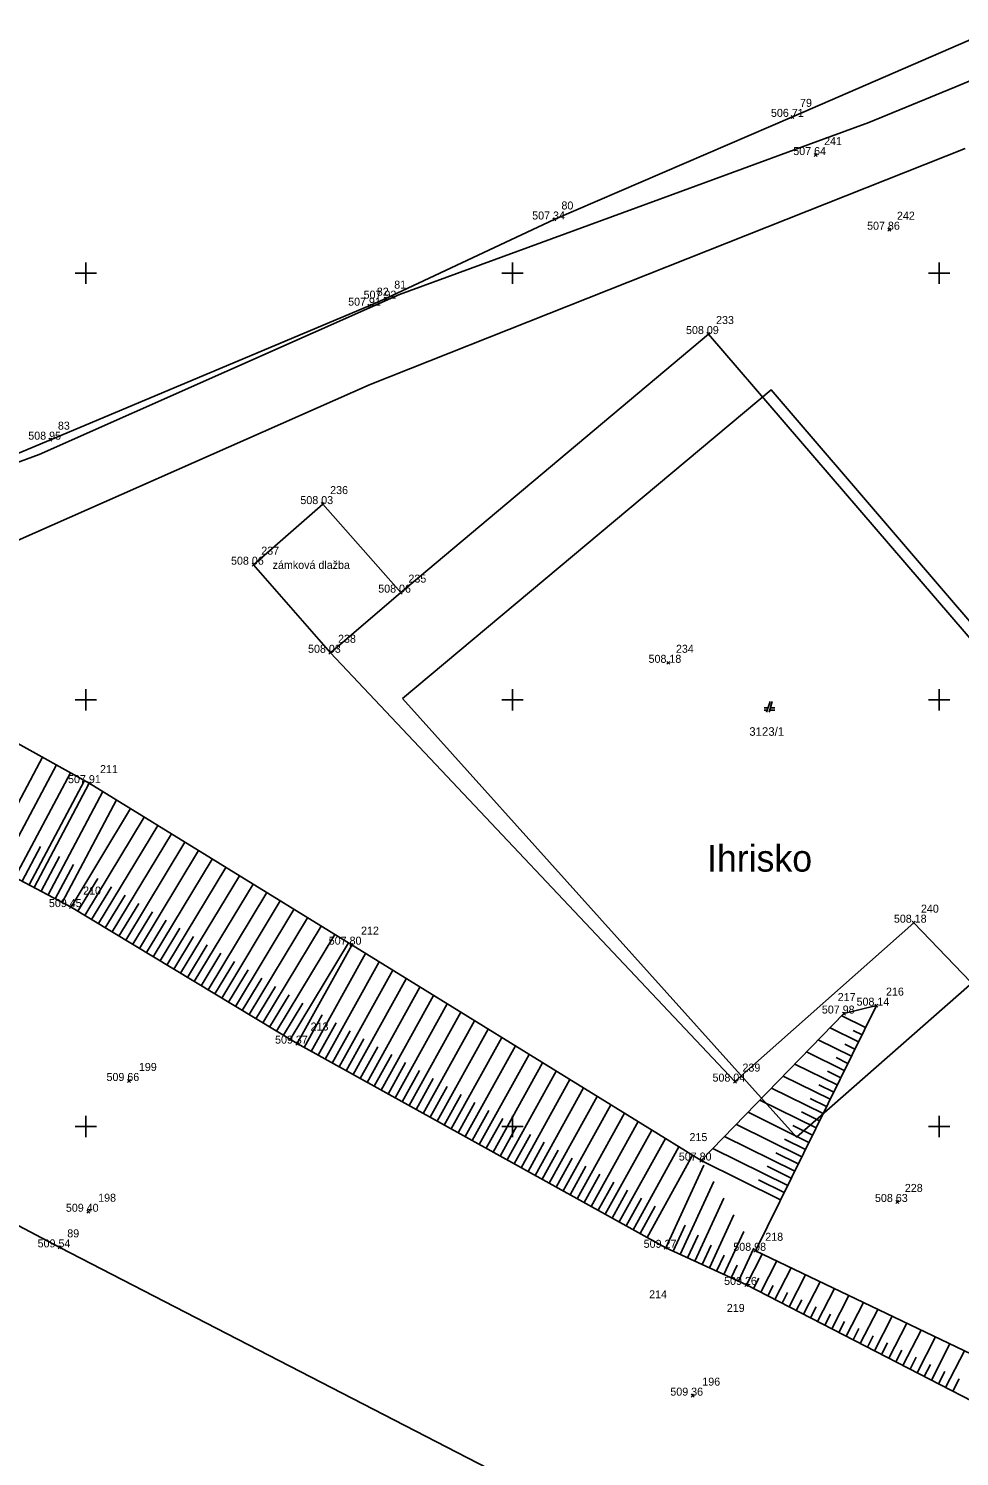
# Model space of a CAD drawing. Extents: x -408550 to -407654, y -1233019 to -1231230.
# Drawn here: x -408082.7 to -408039.1, y -1232035.5 to -1231968.5 of the extents above; entities that cross this region are included whole.
import ezdxf

# ---------------------------------------------------------------- set-up
doc = ezdxf.new("R2010")
doc.units = 0
for name, color, linetype in [('Level 1', 7, 'Continuous'), ('Level 12', 7, 'Continuous'), ('Level 13', 7, 'Continuous'), ('Level 16', 7, 'Continuous'), ('Level 23', 7, 'Continuous'), ('Level 26', 7, 'Continuous'), ('Level 28', 7, 'Continuous'), ('Level 4', 7, 'Continuous'), ('Level 40', 7, 'Continuous'), ('Level 5', 7, 'Continuous')]:
    doc.layers.add(name, color=color, linetype=linetype)

msp = doc.modelspace()

# ---------------------------------------------------------------- linework, layer by layer
at = {"layer": 'Level 1'}
for p, q in [((-408080, -1231979.5), (-408080, -1231980.5)), ((-408060, -1231979.5), (-408060, -1231980.5)), ((-408040, -1231979.5), (-408040, -1231980.5)), ((-408080.5, -1231980), (-408079.5, -1231980)), ((-408060.5, -1231980), (-408059.5, -1231980)), ((-408040.5, -1231980), (-408039.5, -1231980)), ((-408080.5, -1232000), (-408079.5, -1232000)), ((-408080, -1231999.5), (-408080, -1232000.5)), ((-408060.5, -1232000), (-408059.5, -1232000)), ((-408060, -1231999.5), (-408060, -1232000.5)), ((-408040.5, -1232000), (-408039.5, -1232000)), ((-408040, -1231999.5), (-408040, -1232000.5)), ((-408080.5, -1232020), (-408079.5, -1232020)), ((-408080, -1232019.5), (-408080, -1232020.5)), ((-408060.5, -1232020), (-408059.5, -1232020)), ((-408060, -1232019.5), (-408060, -1232020.5)), ((-408040.5, -1232020), (-408039.5, -1232020)), ((-408040, -1232019.5), (-408040, -1232020.5))]:
    msp.add_line(p, q, dxfattribs=at)
for points in [[(-408035.38, -1231969.67), (-408039.27, -1231971.28), (-408043.31, -1231972.94), (-408046.8, -1231974.23), (-408049.99, -1231975.4), (-408053.1, -1231976.54), (-408059.29, -1231978.81), (-408065.3, -1231981.01), (-408073.39, -1231984.6), (-408082.2, -1231988.5), (-408089.6, -1231991.22), (-408096.11, -1231993.62), (-408102.27, -1231996.2), (-408108.37, -1231998.76), (-408114.71, -1232001.42)], [(-408114.71, -1232001.42), (-408108.37, -1231998.76), (-408102.27, -1231996.2), (-408096.11, -1231993.62), (-408089.6, -1231991.22), (-408082.2, -1231988.5), (-408073.39, -1231984.6), (-408065.3, -1231981.01), (-408059.29, -1231978.81), (-408053.1, -1231976.54), (-408049.99, -1231975.4), (-408046.8, -1231974.23), (-408043.31, -1231972.94), (-408039.27, -1231971.28), (-408035.38, -1231969.67)], [(-408038.79, -1231974.16), (-408066.68, -1231985.23), (-408086.61, -1231994.04), (-408100.15, -1231999.15), (-408125.76, -1232010.23), (-408127.68, -1232010.95), (-408133.36, -1232013.08), (-408146.37, -1232017.08), (-408165.18, -1232022.99)], [(-408035.27, -1232074.4), (-408044.77, -1232071.09), (-408050.33, -1232069.15), (-408058.02, -1232063.36), (-408068.11, -1232055.77), (-408073.77, -1232051.51), (-408078.94, -1232047.62), (-408084.51, -1232043.43), (-408090.17, -1232039.17), (-408096, -1232034.78), (-408102.42, -1232029.95), (-408115.87, -1232019.83), (-408127.68, -1232010.95), (-408125.76, -1232010.23), (-408100.15, -1231999.15), (-408086.61, -1231994.04), (-408066.68, -1231985.23), (-408038.79, -1231974.16)], [(-408048.034, -1232000.383), (-408048.204, -1232000.383)], [(-408048.204, -1232000.483), (-408048.069, -1232000.483)], [(-408047.929, -1232000.083), (-408048.104, -1232000.583)], [(-408047.979, -1232000.583), (-408047.829, -1232000.083)], [(-408047.949, -1232000.483), (-408047.704, -1232000.483)], [(-408047.704, -1232000.383), (-408047.919, -1232000.383)]]:
    msp.add_lwpolyline(points, dxfattribs=at)
at = {"layer": 'Level 12'}
msp.add_lwpolyline([(-408037.34, -1231968.54), (-408046.88, -1231972.68), (-408058.05, -1231977.49), (-408065.95, -1231981.2), (-408066.72, -1231981.53), (-408081.67, -1231987.81), (-408090.6, -1231991.55), (-408110.81, -1232000.25), (-408118.15, -1232003.47), (-408117.7, -1232004.22), (-408114.75, -1232007.99), (-408081.23, -1232025.67), (-408056.73, -1232038.31), (-408035.18, -1232049.43)], dxfattribs=at)
at = {"layer": 'Level 13'}
for p, q in [((-408084.654, -1232007.628), (-408082.044, -1232002.694)), ((-408083.991, -1232007.979), (-408081.388, -1232003.057)), ((-408083.329, -1232008.33), (-408080.732, -1232003.421)), ((-408082.666, -1232008.68), (-408080.076, -1232003.785)), ((-408082.437, -1232008.801), (-408079.85, -1232003.91)), ((-408081.774, -1232009.152), (-408079.21, -1232004.304)), ((-408081.111, -1232009.502), (-408078.57, -1232004.699)), ((-408080.7, -1232009.72), (-408077.913, -1232005.104)), ((-408080.058, -1232010.108), (-408077.275, -1232005.498)), ((-408079.416, -1232010.495), (-408076.636, -1232005.891)), ((-408078.774, -1232010.883), (-408075.998, -1232006.285)), ((-408078.132, -1232011.271), (-408075.359, -1232006.678)), ((-408082.997, -1232008.505), (-408082.134, -1232006.873)), ((-408082.106, -1232008.976), (-408081.248, -1232007.355)), ((-408077.49, -1232011.658), (-408074.721, -1232007.072)), ((-408081.443, -1232009.327), (-408080.593, -1232007.72)), ((-408076.848, -1232012.046), (-408074.082, -1232007.466)), ((-408076.206, -1232012.434), (-408073.444, -1232007.859)), ((-408080.379, -1232009.914), (-408079.452, -1232008.378)), ((-408075.564, -1232012.821), (-408072.805, -1232008.253)), ((-408074.922, -1232013.209), (-408072.167, -1232008.646)), ((-408079.737, -1232010.301), (-408078.811, -1232008.767)), ((-408079.095, -1232010.689), (-408078.17, -1232009.157)), ((-408074.28, -1232013.597), (-408071.528, -1232009.04)), ((-408078.453, -1232011.077), (-408077.529, -1232009.547)), ((-408077.811, -1232011.464), (-408076.888, -1232009.936)), ((-408073.637, -1232013.984), (-408070.89, -1232009.433)), ((-408072.995, -1232014.372), (-408070.251, -1232009.827)), ((-408077.169, -1232011.852), (-408076.247, -1232010.326)), ((-408076.527, -1232012.24), (-408075.606, -1232010.715)), ((-408072.353, -1232014.759), (-408069.613, -1232010.221)), ((-408071.711, -1232015.147), (-408068.974, -1232010.614)), ((-408075.885, -1232012.627), (-408074.966, -1232011.105)), ((-408071.069, -1232015.535), (-408068.336, -1232011.008)), ((-408075.243, -1232013.015), (-408074.325, -1232011.495)), ((-408074.601, -1232013.403), (-408073.684, -1232011.884)), ((-408070.427, -1232015.922), (-408067.698, -1232011.401)), ((-408070.1, -1232016.12), (-408067.54, -1232011.498)), ((-408069.444, -1232016.483), (-408066.901, -1232011.892)), ((-408073.958, -1232013.79), (-408073.043, -1232012.274)), ((-408073.316, -1232014.178), (-408072.402, -1232012.664)), ((-408068.788, -1232016.847), (-408066.262, -1232012.286)), ((-408068.132, -1232017.21), (-408065.623, -1232012.681)), ((-408072.674, -1232014.566), (-408071.761, -1232013.053)), ((-408067.476, -1232017.573), (-408064.984, -1232013.075)), ((-408072.032, -1232014.953), (-408071.12, -1232013.443)), ((-408071.39, -1232015.341), (-408070.48, -1232013.832)), ((-408066.819, -1232017.937), (-408064.345, -1232013.469)), ((-408066.163, -1232018.3), (-408063.706, -1232013.863)), ((-408070.748, -1232015.729), (-408069.839, -1232014.222)), ((-408065.507, -1232018.664), (-408063.067, -1232014.257)), ((-408064.851, -1232019.027), (-408062.428, -1232014.651)), ((-408069.772, -1232016.302), (-408068.922, -1232014.768)), ((-408069.116, -1232016.665), (-408068.272, -1232015.141)), ((-408064.195, -1232019.39), (-408061.789, -1232015.045)), ((-408043.788, -1232016.038), (-408045.121, -1232015.38)), ((-408043.456, -1232015.366), (-408044.572, -1232014.815)), ((-408068.46, -1232017.028), (-408067.622, -1232015.515)), ((-408067.804, -1232017.392), (-408066.971, -1232015.889)), ((-408063.539, -1232019.754), (-408061.15, -1232015.439)), ((-408062.883, -1232020.117), (-408060.511, -1232015.834)), ((-408044.12, -1232016.711), (-408045.67, -1232015.946)), ((-408043.622, -1232015.702), (-408044.03, -1232015.501)), ((-408067.148, -1232017.755), (-408066.321, -1232016.262)), ((-408066.491, -1232018.118), (-408065.67, -1232016.636)), ((-408062.227, -1232020.48), (-408059.872, -1232016.228)), ((-408061.571, -1232020.844), (-408059.232, -1232016.622)), ((-408044.452, -1232017.383), (-408046.219, -1232016.511)), ((-408043.954, -1232016.374), (-408044.434, -1232016.137)), ((-408065.835, -1232018.482), (-408065.02, -1232017.009)), ((-408065.179, -1232018.845), (-408064.369, -1232017.383)), ((-408060.915, -1232021.207), (-408058.593, -1232017.016)), ((-408060.258, -1232021.57), (-408057.954, -1232017.41)), ((-408044.784, -1232018.056), (-408046.768, -1232017.077)), ((-408044.618, -1232017.719), (-408045.242, -1232017.411)), ((-408044.286, -1232017.047), (-408044.838, -1232016.774)), ((-408064.523, -1232019.209), (-408063.719, -1232017.757)), ((-408059.602, -1232021.934), (-408057.315, -1232017.804)), ((-408045.116, -1232018.728), (-408047.317, -1232017.642)), ((-408044.95, -1232018.392), (-408045.646, -1232018.048)), ((-408063.867, -1232019.572), (-408063.069, -1232018.13)), ((-408063.211, -1232019.935), (-408062.418, -1232018.504)), ((-408058.946, -1232022.297), (-408056.676, -1232018.198)), ((-408058.29, -1232022.661), (-408056.037, -1232018.592)), ((-408045.447, -1232019.401), (-408047.866, -1232018.207)), ((-408045.281, -1232019.065), (-408046.051, -1232018.685)), ((-408062.555, -1232020.299), (-408061.768, -1232018.877)), ((-408061.899, -1232020.662), (-408061.117, -1232019.251)), ((-408057.634, -1232023.024), (-408055.398, -1232018.986)), ((-408056.978, -1232023.387), (-408054.759, -1232019.381)), ((-408046.111, -1232020.746), (-408048.964, -1232019.338)), ((-408045.779, -1232020.073), (-408048.415, -1232018.773)), ((-408045.613, -1232019.737), (-408046.455, -1232019.322)), ((-408061.243, -1232021.025), (-408060.467, -1232019.625)), ((-408060.587, -1232021.389), (-408059.816, -1232019.998)), ((-408056.322, -1232023.751), (-408054.12, -1232019.775)), ((-408046.443, -1232021.419), (-408049.513, -1232019.904)), ((-408045.945, -1232020.41), (-408046.859, -1232019.959)), ((-408059.93, -1232021.752), (-408059.166, -1232020.372)), ((-408059.274, -1232022.115), (-408058.516, -1232020.745)), ((-408055.666, -1232024.114), (-408053.481, -1232020.169)), ((-408055.01, -1232024.477), (-408052.842, -1232020.563)), ((-408046.775, -1232022.091), (-408050.062, -1232020.469)), ((-408046.277, -1232021.082), (-408047.263, -1232020.596)), ((-408058.618, -1232022.479), (-408057.865, -1232021.119)), ((-408054.354, -1232024.841), (-408052.203, -1232020.957)), ((-408053.697, -1232025.204), (-408051.564, -1232021.351)), ((-408047.107, -1232022.764), (-408050.611, -1232021.035)), ((-408046.609, -1232021.755), (-408047.667, -1232021.233)), ((-408057.962, -1232022.842), (-408057.215, -1232021.493)), ((-408057.306, -1232023.206), (-408056.564, -1232021.866)), ((-408052.82, -1232025.69), (-408051.034, -1232021.81)), ((-408047.439, -1232023.436), (-408051.16, -1232021.6)), ((-408046.941, -1232022.427), (-408048.072, -1232021.869)), ((-408056.65, -1232023.569), (-408055.914, -1232022.24)), ((-408055.994, -1232023.932), (-408055.263, -1232022.613)), ((-408052.139, -1232026.004), (-408050.567, -1232022.588)), ((-408047.273, -1232023.1), (-408048.476, -1232022.506)), ((-408055.338, -1232024.296), (-408054.613, -1232022.987)), ((-408054.682, -1232024.659), (-408053.963, -1232023.361)), ((-408051.457, -1232026.317), (-408050.099, -1232023.367)), ((-408054.026, -1232025.022), (-408053.312, -1232023.734)), ((-408052.479, -1232025.847), (-408051.92, -1232024.632)), ((-408050.776, -1232026.631), (-408049.632, -1232024.145)), ((-408051.798, -1232026.16), (-408051.31, -1232025.1)), ((-408050.095, -1232026.944), (-408049.164, -1232024.923)), ((-408051.117, -1232026.474), (-408050.7, -1232025.569)), ((-408050.436, -1232026.788), (-408050.09, -1232026.037)), ((-408049.414, -1232027.258), (-408048.697, -1232025.702)), ((-408049.04, -1232027.43), (-408048.297, -1232025.985)), ((-408049.754, -1232027.101), (-408049.48, -1232026.506)), ((-408048.373, -1232027.773), (-408047.62, -1232026.308)), ((-408047.706, -1232028.116), (-408046.943, -1232026.632)), ((-408048.707, -1232027.602), (-408048.457, -1232027.117)), ((-408048.04, -1232027.945), (-408047.787, -1232027.454)), ((-408047.039, -1232028.459), (-408046.266, -1232026.956)), ((-408046.372, -1232028.802), (-408045.589, -1232027.28)), ((-408047.373, -1232028.288), (-408047.117, -1232027.79)), ((-408046.706, -1232028.631), (-408046.447, -1232028.127)), ((-408045.705, -1232029.145), (-408044.912, -1232027.604)), ((-408045.038, -1232029.488), (-408044.236, -1232027.927)), ((-408046.039, -1232028.974), (-408045.776, -1232028.463)), ((-408044.371, -1232029.831), (-408043.559, -1232028.251)), ((-408043.704, -1232030.174), (-408042.882, -1232028.575)), ((-408045.372, -1232029.317), (-408045.106, -1232028.8)), ((-408044.705, -1232029.66), (-408044.436, -1232029.137)), ((-408043.037, -1232030.517), (-408042.205, -1232028.899)), ((-408042.37, -1232030.86), (-408041.528, -1232029.223)), ((-408044.038, -1232030.003), (-408043.766, -1232029.473)), ((-408043.371, -1232030.346), (-408043.095, -1232029.81)), ((-408041.703, -1232031.203), (-408040.851, -1232029.546)), ((-408041.036, -1232031.546), (-408040.174, -1232029.87)), ((-408042.704, -1232030.689), (-408042.425, -1232030.147)), ((-408042.037, -1232031.032), (-408041.755, -1232030.483)), ((-408040.369, -1232031.889), (-408039.498, -1232030.194)), ((-408039.702, -1232032.232), (-408038.821, -1232030.518)), ((-408041.37, -1232031.375), (-408041.085, -1232030.82)), ((-408040.703, -1232031.718), (-408040.414, -1232031.156)), ((-408040.036, -1232032.061), (-408039.744, -1232031.493)), ((-408039.369, -1232032.404), (-408039.074, -1232031.83))]:
    msp.add_line(p, q, dxfattribs=at)
msp.add_lwpolyline([(-408035.39, -1232034.45), (-408049.04, -1232027.43), (-408052.82, -1232025.69), (-408070.1, -1232016.12), (-408080.7, -1232009.72), (-408092.61, -1232003.42), (-408096.29, -1232000.56), (-408102.47, -1232004.59), (-408106.47, -1232009.8), (-408087.03, -1232020.46), (-408087.63, -1232021.39), (-408109.65, -1232009.06), (-408104.69, -1232002.7), (-408096.58, -1231999.24), (-408090.6, -1231997.95), (-408079.85, -1232003.91), (-408067.57, -1232011.48), (-408051.16, -1232021.6), (-408044.47, -1232014.71), (-408042.95, -1232014.34), (-408048.62, -1232025.83), (-408034.51, -1232032.58)], dxfattribs=at)
at = {"layer": 'Level 16'}
msp.add_line((-408065.24, -1231994.98), (-408068.54, -1231997.8), dxfattribs=at)
msp.add_lwpolyline([(-408049.58, -1232017.9), (-408041.2, -1232010.45), (-408036.62, -1232015.22), (-408033.75, -1232013.01), (-408037.85, -1232007.63), (-408033.09, -1232003.49), (-408050.82, -1231982.86), (-408065.24, -1231994.98), (-408068.9, -1231990.83), (-408072.14, -1231993.67), (-408068.54, -1231997.8)], close=True, dxfattribs=at)
at = {"layer": 'Level 23'}
for points in [[(-408046.811, -1231972.749), (-408046.949, -1231972.611)], [(-408046.949, -1231972.749), (-408046.811, -1231972.611)], [(-408045.731, -1231974.539), (-408045.869, -1231974.401)], [(-408045.869, -1231974.539), (-408045.731, -1231974.401)], [(-408057.981, -1231977.559), (-408058.119, -1231977.421)], [(-408058.119, -1231977.559), (-408057.981, -1231977.421)], [(-408042.271, -1231978.039), (-408042.409, -1231977.901)], [(-408042.409, -1231978.039), (-408042.271, -1231977.901)], [(-408065.881, -1231981.269), (-408066.019, -1231981.131)], [(-408066.019, -1231981.269), (-408065.881, -1231981.131)], [(-408066.651, -1231981.599), (-408066.789, -1231981.461)], [(-408066.789, -1231981.599), (-408066.651, -1231981.461)], [(-408050.751, -1231982.929), (-408050.889, -1231982.791)], [(-408050.889, -1231982.929), (-408050.751, -1231982.791)], [(-408081.601, -1231987.879), (-408081.739, -1231987.741)], [(-408081.739, -1231987.879), (-408081.601, -1231987.741)], [(-408068.831, -1231990.899), (-408068.969, -1231990.761)], [(-408068.969, -1231990.899), (-408068.831, -1231990.761)], [(-408072.071, -1231993.739), (-408072.209, -1231993.601)], [(-408072.209, -1231993.739), (-408072.071, -1231993.601)], [(-408065.171, -1231995.049), (-408065.309, -1231994.911)], [(-408065.309, -1231995.049), (-408065.171, -1231994.911)], [(-408068.471, -1231997.869), (-408068.609, -1231997.731)], [(-408068.609, -1231997.869), (-408068.471, -1231997.731)], [(-408052.631, -1231998.339), (-408052.769, -1231998.201)], [(-408052.769, -1231998.339), (-408052.631, -1231998.201)], [(-408079.781, -1232003.979), (-408079.919, -1232003.841)], [(-408079.919, -1232003.979), (-408079.781, -1232003.841)], [(-408080.631, -1232009.789), (-408080.769, -1232009.651)], [(-408080.769, -1232009.789), (-408080.631, -1232009.651)], [(-408041.131, -1232010.519), (-408041.269, -1232010.381)], [(-408041.269, -1232010.519), (-408041.131, -1232010.381)], [(-408067.501, -1232011.549), (-408067.639, -1232011.411)], [(-408067.639, -1232011.549), (-408067.501, -1232011.411)], [(-408044.401, -1232014.779), (-408044.539, -1232014.641)], [(-408044.539, -1232014.779), (-408044.401, -1232014.641)], [(-408042.881, -1232014.409), (-408043.019, -1232014.271)], [(-408043.019, -1232014.409), (-408042.881, -1232014.271)], [(-408070.031, -1232016.189), (-408070.169, -1232016.051)], [(-408070.169, -1232016.189), (-408070.031, -1232016.051)], [(-408077.911, -1232017.939), (-408078.049, -1232017.801)], [(-408078.049, -1232017.939), (-408077.911, -1232017.801)], [(-408049.511, -1232017.969), (-408049.649, -1232017.831)], [(-408049.649, -1232017.969), (-408049.511, -1232017.831)], [(-408051.091, -1232021.669), (-408051.229, -1232021.531)], [(-408051.229, -1232021.669), (-408051.091, -1232021.531)], [(-408079.821, -1232024.069), (-408079.959, -1232023.931)], [(-408079.959, -1232024.069), (-408079.821, -1232023.931)], [(-408041.901, -1232023.609), (-408042.039, -1232023.471)], [(-408042.039, -1232023.609), (-408041.901, -1232023.471)], [(-408081.161, -1232025.739), (-408081.299, -1232025.601)], [(-408081.299, -1232025.739), (-408081.161, -1232025.601)], [(-408052.751, -1232025.759), (-408052.889, -1232025.621)], [(-408052.889, -1232025.759), (-408052.751, -1232025.621)], [(-408048.551, -1232025.899), (-408048.689, -1232025.761)], [(-408048.689, -1232025.899), (-408048.551, -1232025.761)], [(-408048.971, -1232027.499), (-408049.109, -1232027.361)], [(-408049.109, -1232027.499), (-408048.971, -1232027.361)], [(-408051.491, -1232032.689), (-408051.629, -1232032.551)], [(-408051.629, -1232032.689), (-408051.491, -1232032.551)]]:
    msp.add_lwpolyline(points, dxfattribs=at)
at = {"layer": 'Level 4'}
msp.add_lwpolyline([(-408035.27, -1232074.4), (-408044.77, -1232071.09), (-408050.33, -1232069.15), (-408058.02, -1232063.36), (-408068.11, -1232055.77), (-408073.77, -1232051.51), (-408078.94, -1232047.62), (-408084.51, -1232043.43), (-408090.17, -1232039.17), (-408096, -1232034.78), (-408102.42, -1232029.95), (-408115.87, -1232019.83), (-408127.68, -1232010.95), (-408125.76, -1232010.23), (-408100.15, -1231999.15), (-408086.61, -1231994.04), (-408066.68, -1231985.23), (-408038.79, -1231974.16)], dxfattribs=at)
at = {"layer": 'Level 5'}
msp.add_line((-408046.69, -1232020.5), (-408065.17, -1231999.95), dxfattribs=at)
msp.add_lwpolyline([(-408065.17, -1231999.95), (-408047.88, -1231985.48), (-408030.21, -1232006.09), (-408034.89, -1232010.12), (-408030.45, -1232016.04), (-408033.3, -1232018.35), (-408038.07, -1232012.92), (-408046.69, -1232020.5)], dxfattribs=at)

# ---------------------------------------------------------------- texts
at = {"layer": 'Level 1'}
msp.add_text('3123/1', height=0.4, dxfattribs=at).set_placement((-408048.908, -1232001.69))
at = {"layer": 'Level 26'}
for s, p in [('79', (-408046.527, -1231972.21)), ('241', (-408045.399, -1231974)), ('80', (-408057.712, -1231977.02)), ('242', (-408041.984, -1231977.5)), ('81', (-408065.551, -1231980.73)), ('82', (-408066.366, -1231981.06)), ('233', (-408050.464, -1231982.39)), ('83', (-408081.316, -1231987.34)), ('236', (-408068.554, -1231990.36)), ('237', (-408071.784, -1231993.2)), ('235', (-408064.884, -1231994.51)), ('238', (-408068.184, -1231997.33)), ('234', (-408052.344, -1231997.8)), ('211', (-408079.343, -1232003.44)), ('210', (-408080.133, -1232009.133)), ('240', (-408040.86, -1232009.98)), ('212', (-408067.107, -1232011.01)), ('217', (-408044.761, -1232014.124)), ('216', (-408042.498, -1232013.87)), ('213', (-408069.47, -1232015.505)), ('199', (-408077.52, -1232017.4)), ('239', (-408049.225, -1232017.43)), ('215', (-408051.709, -1232020.688)), ('228', (-408041.614, -1232023.07)), ('198', (-408079.429, -1232023.53)), ('89', (-408080.877, -1232025.2)), ('218', (-408048.157, -1232025.36)), ('214', (-408053.6, -1232028.057)), ('219', (-408049.96, -1232028.696)), ('196', (-408051.109, -1232032.15))]:
    msp.add_text(s, height=0.375, dxfattribs=at).set_placement(p)
at = {"layer": 'Level 28'}
for s, height, p in [('zámková dlažba', 0.375, (-408071.251, -1231993.869)), ('Ihrisko', 1.25, (-408050.886, -1232008.056))]:
    msp.add_text(s, height=height, dxfattribs=at).set_placement(p)
at = {"layer": 'Level 40'}
for s, p in [('506 71', (-408047.89, -1231972.68)), ('507 64', (-408046.844, -1231974.47)), ('507 34', (-408059.084, -1231977.49)), ('507 86', (-408043.384, -1231977.97)), ('507 91', (-408067.711, -1231981.53)), ('507 92', (-408066.985, -1231981.2)), ('508 09', (-408051.872, -1231982.86)), ('508 95', (-408082.705, -1231987.81)), ('508 03', (-408069.95, -1231990.83)), ('508 06', (-408073.201, -1231993.67)), ('508 06', (-408066.301, -1231994.98)), ('508 03', (-408069.59, -1231997.8)), ('508 18', (-408053.628, -1231998.27)), ('507 91', (-408080.841, -1232003.91)), ('509 45', (-408081.737, -1232009.72)), ('508 18', (-408042.128, -1232010.45)), ('507 80', (-408068.62, -1232011.48)), ('508 14', (-408043.878, -1232014.34)), ('507 98', (-408045.505, -1232014.71)), ('509 37', (-408071.137, -1232016.12)), ('509 66', (-408079.038, -1232017.87)), ('508 04', (-408050.63, -1232017.9)), ('507 80', (-408052.21, -1232021.6)), ('508 63', (-408043.014, -1232023.54)), ('509 40', (-408080.943, -1232024)), ('509 54', (-408082.267, -1232025.67)), ('509 27', (-408053.857, -1232025.69)), ('508 98', (-408049.655, -1232025.83)), ('509 26', (-408050.087, -1232027.43)), ('509 36', (-408052.607, -1232032.62))]:
    msp.add_text(s, height=0.375, dxfattribs=at).set_placement(p)

doc.saveas('drawing.dxf')
